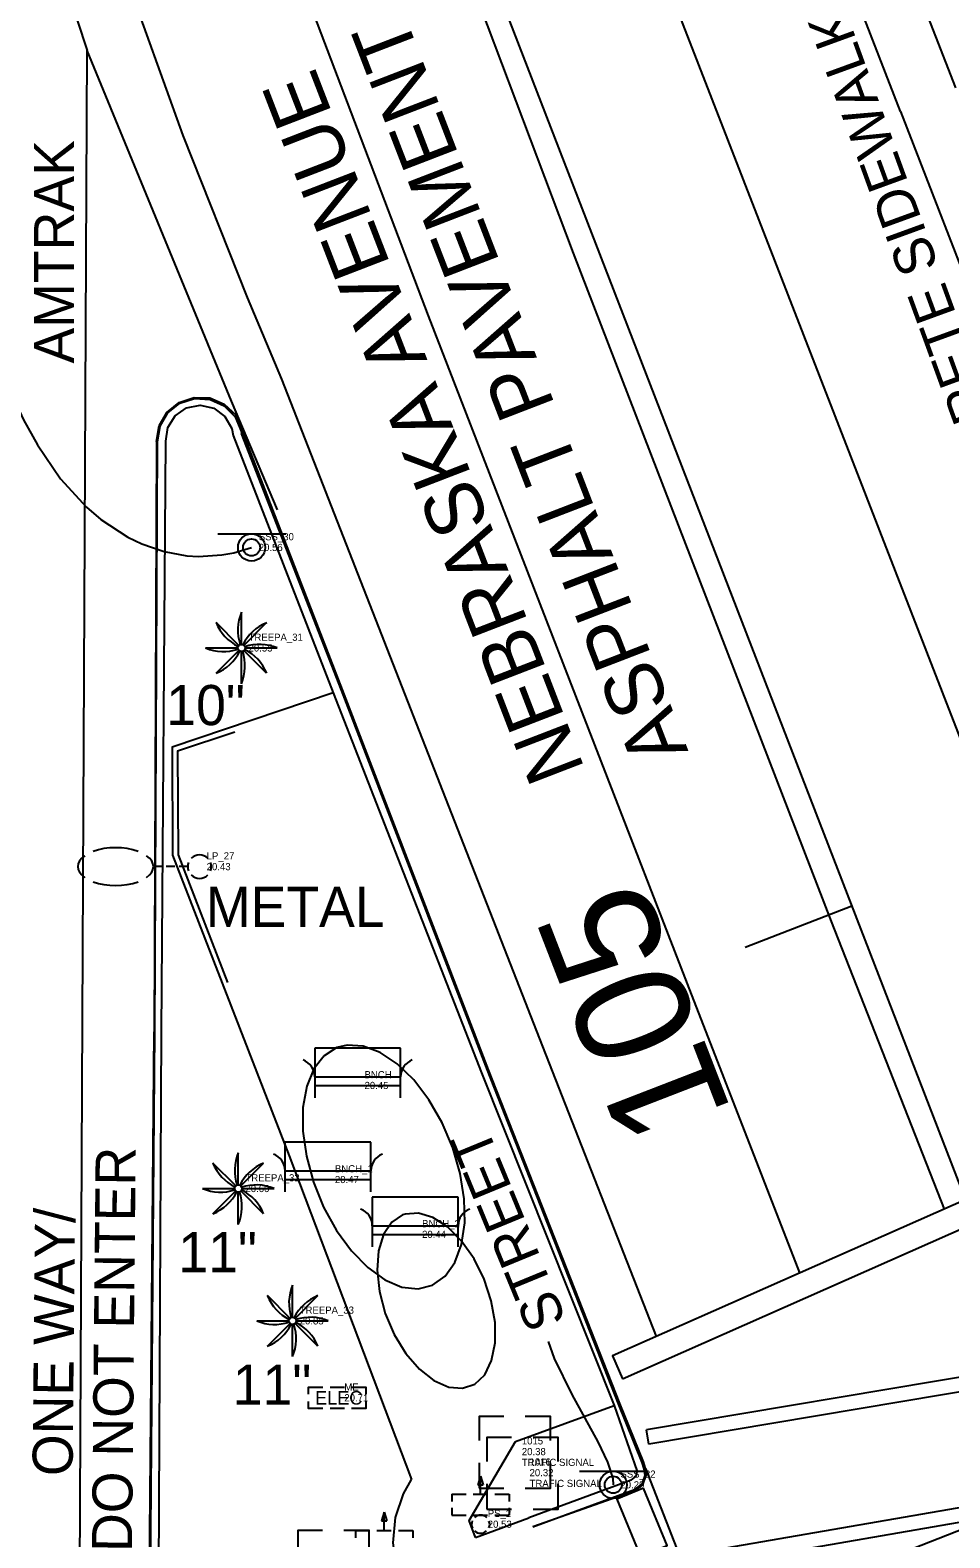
# Model space of a CAD drawing. Extents: x 509744 to 512285, y 1314862 to 1316822.
# Drawn here: x 510479.2 to 510543.5, y 1315469.6 to 1315574.9 of the extents above; entities that cross this region are included whole.
import ezdxf

# ---------------------------------------------------------------- set-up
doc = ezdxf.new("R2010")
doc.units = 0
for name, color, linetype in [('BaselineSurvey', 7, 'Continuous'), ('Bench_ep', 7, 'Continuous'), ('BusStop_ep', 7, 'Continuous'), ('CGBack_ep', 7, 'Continuous'), ('CGep_ep', 7, 'Continuous'), ('CGFace_ep', 7, 'Continuous'), ('ConcSlabs_ep', 7, 'Continuous'), ('CurbRampWarning_ep', 7, 'Continuous'), ('ElecAer_ep', 7, 'Continuous'), ('Luminaire_ep', 7, 'Continuous'), ('MeterElec_ep', 7, 'Continuous'), ('PavtAsphalt_ep', 7, 'Continuous'), ('PedSignal_ep', 7, 'Continuous'), ('PMRK_ep', 7, 'Continuous'), ('PullBox_ep', 7, 'Continuous'), ('Railing_ep', 7, 'Continuous'), ('SignSingle_ep', 7, 'Continuous'), ('TextBLStation', 7, 'Continuous'), ('TextElevLabel', 7, 'Continuous'), ('TextPtLabel', 7, 'Continuous'), ('TextSurveyLabel', 7, 'Continuous'), ('TextTopoLabel_ep', 7, 'Continuous'), ('TextUtilLabel_ep', 7, 'Continuous'), ('TreePalm_ep', 7, 'Continuous')]:
    doc.layers.add(name, color=color, linetype=linetype)

msp = doc.modelspace()

# ---------------------------------------------------------------- linework, layer by layer
at = {"layer": 'BaselineSurvey'}
for p, q in [((510773.86, 1314900.51), (510499.95, 1315608.68)), ((510536.67, 1315513.74), (510529.21, 1315510.85))]:
    msp.add_line(p, q, dxfattribs=at)
at = {"layer": 'Bench_ep'}
for p, q in [((510505.13, 1315503.82), (510499.13, 1315503.82)), ((510499.13, 1315503.82), (510499.13, 1315500.34)), ((510505.13, 1315500.34), (510505.13, 1315503.82)), ((510499.13, 1315501.81), (510505.13, 1315501.81)), ((510499.13, 1315501.21), (510505.13, 1315501.21)), ((510503.05, 1315497.25), (510497.05, 1315497.25)), ((510497.05, 1315497.25), (510497.05, 1315493.77)), ((510503.05, 1315493.77), (510503.05, 1315497.25)), ((510497.05, 1315495.25), (510503.05, 1315495.25)), ((510497.05, 1315494.64), (510503.05, 1315494.64)), ((510509.15, 1315493.41), (510503.15, 1315493.41)), ((510503.15, 1315493.41), (510503.15, 1315489.94)), ((510509.15, 1315489.94), (510509.15, 1315493.41)), ((510503.15, 1315491.41), (510509.15, 1315491.41)), ((510503.15, 1315490.81), (510509.15, 1315490.81))]:
    msp.add_line(p, q, dxfattribs=at)
for centre, start, end in [((510497.87, 1315501.81), 0.2359, 69.1544), ((510506.39, 1315501.81), 110.8456, 179.7641), ((510495.8, 1315495.24), 0.2359, 69.1544), ((510504.31, 1315495.24), 110.8456, 179.7641), ((510501.89, 1315491.4), 0.2359, 69.1544), ((510510.41, 1315491.4), 110.8456, 179.7641)]:
    msp.add_arc(centre, 1.26, start, end, dxfattribs=at)
at = {"layer": 'BusStop_ep'}
for points in [[(510500.68, 1315503.85), (510499.78, 1315503.28), (510499.06, 1315502.37), (510498.57, 1315501.15), (510498.31, 1315499.68), (510498.31, 1315498.02), (510498.55, 1315496.26), (510499.04, 1315494.46), (510499.75, 1315492.71), (510500.64, 1315491.08), (510501.69, 1315489.65), (510502.83, 1315488.49), (510504.02, 1315487.63), (510505.21, 1315487.13), (510506.35, 1315487.01), (510507.37, 1315487.26), (510508.25, 1315487.88), (510508.93, 1315488.85), (510509.39, 1315490.11), (510509.61, 1315491.61), (510509.58, 1315493.29), (510509.29, 1315495.06), (510508.77, 1315496.86), (510508.03, 1315498.6), (510507.11, 1315500.2), (510506.05, 1315501.59), (510504.9, 1315502.71), (510503.7, 1315503.51), (510502.52, 1315503.96), (510501.4, 1315504.03)], [(510505.27, 1315492.17), (510504.51, 1315491.65), (510503.93, 1315490.8), (510503.59, 1315489.66), (510503.49, 1315488.3), (510503.66, 1315486.82), (510504.06, 1315485.29), (510504.69, 1315483.82), (510505.5, 1315482.49), (510506.44, 1315481.4), (510507.46, 1315480.6), (510508.49, 1315480.14), (510509.46, 1315480.06), (510510.32, 1315480.36), (510511.01, 1315481.01), (510511.49, 1315481.99), (510511.74, 1315483.23), (510511.73, 1315484.65), (510511.47, 1315486.16), (510510.96, 1315487.68), (510510.26, 1315489.1), (510509.39, 1315490.34), (510508.41, 1315491.33), (510507.38, 1315491.99), (510506.37, 1315492.3), (510505.44, 1315492.23)]]:
    msp.add_lwpolyline(points, close=True, dxfattribs=at)
at = {"layer": 'CGBack_ep'}
for p, q in [((510488.42, 1315504.95), (510488.72, 1315546.2)), ((510488.2, 1315460.01), (510488.42, 1315504.95)), ((510521.24, 1315473.64), (510514.1, 1315471.02))]:
    msp.add_line(p, q, dxfattribs=at)
for points in [[(510488.72, 1315546.2), (510488.86, 1315547.16), (510489.37, 1315547.98), (510490.17, 1315548.53), (510491.12, 1315548.71), (510492.07, 1315548.5), (510492.85, 1315547.93), (510493.34, 1315547.09), (510493.44, 1315546.6)], [(510493.44, 1315546.6), (510500.43, 1315528.63), (510510.78, 1315502.1), (510520.05, 1315478.86), (510521.65, 1315474.26)], [(510521.24, 1315473.64), (510521.6, 1315473.93), (510521.65, 1315474.26)]]:
    msp.add_lwpolyline(points, dxfattribs=at)
at = {"layer": 'CGep_ep'}
msp.add_line((510521.5, 1315472.89), (510514.38, 1315470.39), dxfattribs=at)
for points in [[(510505.13, 1315670.88), (510507.7, 1315664.16), (510525.73, 1315617.49), (510543.9, 1315570.87)], [(510521.5, 1315472.89), (510522.06, 1315473.32), (510522.3, 1315473.99), (510522.24, 1315474.47)]]:
    msp.add_lwpolyline(points, dxfattribs=at)
at = {"layer": 'CGFace_ep'}
for p, q in [((510487.96, 1315504.95), (510488.15, 1315546.17)), ((510487.61, 1315460.03), (510487.96, 1315504.95)), ((510514.38, 1315470.39), (510521.47, 1315472.99))]:
    msp.add_line(p, q, dxfattribs=at)
for points in [[(510488.15, 1315546.17), (510488.32, 1315547.24), (510488.87, 1315548.18), (510489.71, 1315548.86), (510490.74, 1315549.18), (510491.82, 1315549.12), (510492.81, 1315548.67), (510493.56, 1315547.89), (510493.99, 1315546.89), (510494.02, 1315546.74)], [(510522.14, 1315474.44), (510522.02, 1315474.89), (510520.35, 1315478.97), (510511.2, 1315502.28), (510501, 1315528.82), (510494.02, 1315546.74)], [(510521.47, 1315472.99), (510522, 1315473.36), (510522.23, 1315473.97), (510522.14, 1315474.44)]]:
    msp.add_lwpolyline(points, dxfattribs=at)
at = {"layer": 'ConcSlabs_ep'}
for p, q in [((510513.17, 1315476.34), (510520.05, 1315478.86)), ((510510.37, 1315469.63), (510514.1, 1315471.02))]:
    msp.add_line(p, q, dxfattribs=at)
for points in [[(510500.43, 1315528.63), (510489.16, 1315524.82), (510489.2, 1315517.29), (510497.34, 1315496.29), (510505.9, 1315473.7)], [(510510.37, 1315469.63), (510509.93, 1315470.83), (510513.17, 1315476.34)], [(510504.84, 1315467.55), (510504.61, 1315469.28), (510504.77, 1315471.03), (510505.33, 1315472.69), (510505.9, 1315473.7)]]:
    msp.add_lwpolyline(points, dxfattribs=at)
at = {"layer": 'CurbRampWarning_ep'}
msp.add_lwpolyline([(510522.1, 1315473.09), (510520.24, 1315472.32), (510521.9, 1315468.31), (510523.75, 1315469.08)], close=True, dxfattribs=at)
at = {"layer": 'ElecAer_ep'}
msp.add_lwpolyline([(510459.75, 1315437.86), (510522.46, 1315461.64), (510586.32, 1315486.68), (510629.5, 1315501.86)], dxfattribs=at)
at = {"layer": 'Luminaire_ep'}
for p, q in [((510488.46, 1315516.49), (510487.86, 1315516.49)), ((510489.36, 1315516.49), (510488.76, 1315516.49)), ((510490.26, 1315516.49), (510489.66, 1315516.49))]:
    msp.add_line(p, q, dxfattribs=at)
for start, end in [(159.9115, 200.0885), (45, 135), (339.9115, 20.0885), (225, 315)]:
    msp.add_arc((510491.08, 1315516.49), 0.825, start, end, dxfattribs=at)
for start_param, end_param in [(4.075781, 5.348997), (5.668326, 6.898045), (2.526733, 3.756452), (0.934187, 2.207405)]:
    msp.add_ellipse((510485.22, 1315516.49), major_axis=(-2.64, 0), ratio=0.5, start_param=start_param, end_param=end_param, dxfattribs=at)
at = {"layer": 'MeterElec_ep'}
for points in [[(510498.7, 1315479.65), (510498.7, 1315480.15), (510499.7, 1315480.15)], [(510500.2, 1315480.15), (510501.2, 1315480.15)], [(510501.7, 1315480.15), (510502.7, 1315480.15), (510502.7, 1315479.65)], [(510499.7, 1315478.64), (510498.7, 1315478.64), (510498.7, 1315479.15)], [(510501.2, 1315478.64), (510500.2, 1315478.64)], [(510502.7, 1315479.15), (510502.7, 1315478.64), (510501.7, 1315478.64)]]:
    msp.add_lwpolyline(points, dxfattribs=at)
at = {"layer": 'PavtAsphalt_ep'}
for p, q in [((510488.08, 1315546.17), (510487.91, 1315504.95)), ((510487.52, 1315460.04), (510487.91, 1315504.95)), ((510522.24, 1315474.47), (510524.75, 1315468.01))]:
    msp.add_line(p, q, dxfattribs=at)
for points in [[(510488.08, 1315546.17), (510488.25, 1315547.26), (510488.8, 1315548.21), (510489.65, 1315548.91), (510490.7, 1315549.26), (510491.8, 1315549.22), (510492.81, 1315548.79), (510493.61, 1315548.03), (510494.08, 1315547.03), (510494.14, 1315546.77)], [(510522.24, 1315474.47), (510522.1, 1315474.92), (510520.46, 1315479), (510511.27, 1315502.31), (510501.06, 1315528.84), (510494.14, 1315546.77)]]:
    msp.add_lwpolyline(points, dxfattribs=at)
at = {"layer": 'PedSignal_ep'}
for p, q in [((510510.71, 1315473.93), (510510.52, 1315473.33)), ((510510.71, 1315472.66), (510510.71, 1315473.93)), ((510510.71, 1315473.93), (510510.91, 1315473.33)), ((510508.71, 1315472.66), (510509.71, 1315472.66)), ((510508.71, 1315472.66), (510508.71, 1315472.15)), ((510510.21, 1315472.66), (510511.21, 1315472.66)), ((510510.52, 1315473.33), (510510.91, 1315473.33)), ((510511.71, 1315472.66), (510512.71, 1315472.66)), ((510512.71, 1315472.66), (510512.71, 1315472.15)), ((510503.98, 1315471.41), (510503.79, 1315470.81)), ((510503.98, 1315470.13), (510503.98, 1315471.41)), ((510503.98, 1315471.41), (510504.18, 1315470.81)), ((510508.71, 1315471.72), (510508.71, 1315471.21)), ((510512.71, 1315471.72), (510512.71, 1315471.21)), ((510503.79, 1315470.81), (510504.18, 1315470.81)), ((510508.71, 1315471.21), (510509.71, 1315471.21)), ((510510.21, 1315471.21), (510511.21, 1315471.21)), ((510511.71, 1315471.21), (510512.71, 1315471.21)), ((510501.98, 1315470.13), (510502.98, 1315470.13)), ((510501.98, 1315470.13), (510501.98, 1315469.62)), ((510503.48, 1315470.13), (510504.48, 1315470.13)), ((510504.98, 1315470.13), (510505.98, 1315470.13)), ((510505.98, 1315470.13), (510505.98, 1315469.62))]:
    msp.add_line(p, q, dxfattribs=at)
for centre, radius, start, end in [((510510.86, 1315470.59), 0.766, 163.8832, 202.8498), ((510510.71, 1315470.59), 0.616, 45.0677, 132.9221), ((510510.93, 1315470.55), 0.437, 329.0362, 30.9638), ((510510.72, 1315470.55), 0.617, 227.1045, 312.8955)]:
    msp.add_arc(centre, radius, start, end, dxfattribs=at)
at = {"layer": 'PMRK_ep'}
for p, q in [((510482.71, 1315465.66), (510483.24, 1315573.48)), ((510574.85, 1315485.98), (510522.32, 1315477.15)), ((510575.01, 1315484.99), (510522.48, 1315476.16)), ((510583.22, 1315478.49), (510525.97, 1315468.56)), ((510522.48, 1315476.16), (510522.32, 1315477.15)), ((510582.74, 1315477.39), (510526.14, 1315467.57))]:
    msp.add_line(p, q, dxfattribs=at)
for points in [[(510540.07, 1315569.22), (510521.97, 1315615.86), (510503.06, 1315665.15)], [(510467.81, 1315662.15), (510469.21, 1315650.05), (510470.99, 1315638), (510473.18, 1315626.02), (510475.75, 1315614.12), (510478.72, 1315602.31), (510482.07, 1315590.6), (510485.8, 1315579.01), (510489.92, 1315567.55), (510494.4, 1315556.23), (510496.82, 1315550.53)], [(510495.93, 1315650.67), (510510.94, 1315611.1), (510529.06, 1315564.46), (510547.19, 1315517.82), (510555.03, 1315497.85)], [(510465.6, 1315644), (510467.93, 1315630.97), (510470.66, 1315618.01), (510473.77, 1315605.14), (510477.28, 1315592.37), (510481.17, 1315579.72), (510483.24, 1315573.48)], [(510505.16, 1315591.19), (510517.18, 1315559.33), (510535.22, 1315512.66), (510543.12, 1315492.58)], [(510494.86, 1315587.1), (510507.06, 1315554.95), (510525.15, 1315508.31), (510533.01, 1315488.12)], [(510496.53, 1315541.41), (510493.31, 1315548.99), (510483.24, 1315573.48)], [(510540.07, 1315569.22), (510558.16, 1315522.57), (510567.11, 1315499.75)], [(510496.82, 1315550.53), (510515.04, 1315503.94), (510522.98, 1315483.68)]]:
    msp.add_lwpolyline(points, dxfattribs=at)
msp.add_lwpolyline([(510520.64, 1315480.73), (510556.36, 1315496.52), (510555.65, 1315498.12), (510519.93, 1315482.33)], close=True, dxfattribs=at)
at = {"layer": 'PullBox_ep'}
for points in [[(510512.34, 1315478.09), (510510.61, 1315478.09), (510510.61, 1315476.41)], [(510515.61, 1315476.41), (510515.61, 1315478.09), (510513.84, 1315478.09)], [(510512.89, 1315476.62), (510511.15, 1315476.62), (510511.15, 1315474.94)], [(510516.15, 1315474.94), (510516.15, 1315476.62), (510514.39, 1315476.62)], [(510510.61, 1315474.86), (510510.61, 1315473.09)], [(510513.84, 1315473.09), (510515.61, 1315473.09), (510515.61, 1315474.86)], [(510511.15, 1315473.39), (510511.15, 1315471.62)], [(510514.39, 1315471.62), (510516.15, 1315471.62), (510516.15, 1315473.39)], [(510510.61, 1315473.09), (510512.34, 1315473.09)], [(510511.15, 1315471.62), (510512.89, 1315471.62)], [(510499.67, 1315470.12), (510497.94, 1315470.12), (510497.94, 1315468.45)], [(510502.94, 1315468.45), (510502.94, 1315470.12), (510501.17, 1315470.12)]]:
    msp.add_lwpolyline(points, dxfattribs=at)
at = {"layer": 'Railing_ep'}
msp.add_lwpolyline([(510493.55, 1315525.88), (510489.54, 1315524.55), (510489.6, 1315517.32), (510493.03, 1315508.39)], dxfattribs=at)
at = {"layer": 'SignSingle_ep'}
for p, q in [((510492.35, 1315539.73), (510497.1, 1315539.73)), ((510517.62, 1315474.27), (510522.37, 1315474.27))]:
    msp.add_line(p, q, dxfattribs=at)
for centre, radius in [((510494.72, 1315538.78), 0.95), ((510494.72, 1315538.78), 0.594), ((510519.99, 1315473.32), 0.95), ((510519.99, 1315473.32), 0.594)]:
    msp.add_circle(centre, radius, dxfattribs=at)
at = {"layer": 'TextTopoLabel_ep'}
for points in [[(510477.15, 1315551.59), (510478.2, 1315548.94), (510478.79, 1315547.69), (510479.75, 1315545.94), (510481.37, 1315543.58), (510483.19, 1315541.58), (510484.18, 1315540.73), (510486.07, 1315539.5), (510487.06, 1315539.02), (510488.61, 1315538.49), (510490.2, 1315538.2), (510491.01, 1315538.15), (510492.65, 1315538.26), (510493.48, 1315538.41), (510494.72, 1315538.78)], [(510515.45, 1315483.33), (510515.87, 1315482.15), (510517.1, 1315479.62), (510518.9, 1315476.32), (510519.58, 1315474.91), (510519.96, 1315473.76), (510519.99, 1315473.32)]]:
    msp.add_lwpolyline(points, dxfattribs=at)
at = {"layer": 'TreePalm_ep'}
for p, q in [((510493.83, 1315531.94), (510492.24, 1315533.53)), ((510494.01, 1315532.01), (510494.01, 1315534.26)), ((510494.18, 1315531.94), (510495.77, 1315533.53)), ((510491.51, 1315531.76), (510493.76, 1315531.76)), ((510492.24, 1315529.99), (510493.83, 1315531.58)), ((510494.01, 1315529.26), (510494.01, 1315531.51)), ((510495.77, 1315529.99), (510494.18, 1315531.58)), ((510494.26, 1315531.76), (510496.51, 1315531.76)), ((510493.61, 1315494.19), (510492.02, 1315495.78)), ((510493.79, 1315494.26), (510493.79, 1315496.51)), ((510493.96, 1315494.19), (510495.55, 1315495.78)), ((510491.29, 1315494.01), (510493.54, 1315494.01)), ((510492.02, 1315492.25), (510493.61, 1315493.84)), ((510493.79, 1315491.51), (510493.79, 1315493.76)), ((510495.55, 1315492.25), (510493.96, 1315493.84)), ((510494.04, 1315494.01), (510496.29, 1315494.01)), ((510497.58, 1315485.02), (510497.58, 1315487.27)), ((510497.41, 1315484.94), (510495.82, 1315486.53)), ((510497.76, 1315484.94), (510499.35, 1315486.53)), ((510495.08, 1315484.77), (510497.33, 1315484.77)), ((510495.82, 1315483), (510497.41, 1315484.59)), ((510497.58, 1315482.27), (510497.58, 1315484.52)), ((510499.35, 1315483), (510497.76, 1315484.59)), ((510497.83, 1315484.77), (510500.08, 1315484.77))]:
    msp.add_line(p, q, dxfattribs=at)
for centre in [(510494.01, 1315531.76), (510493.79, 1315494.01), (510497.58, 1315484.77)]:
    msp.add_circle(centre, 0.25, dxfattribs=at)
for centre, start, end in [((510495.24, 1315534.77), 202.3801, 243.2114), ((510497.01, 1315533.01), 157.3801, 198.2114), ((510497.01, 1315530.52), 112.3801, 153.2114), ((510492.76, 1315534.76), 247.3801, 288.2114), ((510491, 1315533), 292.3801, 333.2114), ((510491.01, 1315530.51), 337.3801, 18.2114), ((510492.77, 1315528.76), 22.3801, 63.2114), ((510495.26, 1315528.76), 67.3801, 108.2114), ((510495.02, 1315497.02), 202.3801, 243.2114), ((510496.79, 1315495.26), 157.3801, 198.2114), ((510496.79, 1315492.78), 112.3801, 153.2114), ((510492.54, 1315497.01), 247.3801, 288.2114), ((510490.78, 1315495.25), 292.3801, 333.2114), ((510490.79, 1315492.76), 337.3801, 18.2114), ((510492.55, 1315491.01), 22.3801, 63.2114), ((510495.04, 1315491.01), 67.3801, 108.2114), ((510500.58, 1315486.02), 157.3801, 198.2114), ((510498.82, 1315487.77), 202.3801, 243.2114), ((510500.59, 1315483.53), 112.3801, 153.2114), ((510498.83, 1315481.77), 67.3801, 108.2114), ((510496.33, 1315487.77), 247.3801, 288.2114), ((510494.58, 1315486), 292.3801, 333.2114), ((510494.58, 1315483.52), 337.3801, 18.2114), ((510496.35, 1315481.76), 22.3801, 63.2114)]:
    msp.add_arc(centre, 3.25, start, end, dxfattribs=at)

# ---------------------------------------------------------------- texts
at = {"layer": 'BaselineSurvey'}
msp.add_text('105', height=8, rotation=111.1462, dxfattribs=at).set_placement((510528.32, 1315499.27))
at = {"layer": 'MeterElec_ep'}
msp.add_text('ELEC', height=0.95, dxfattribs=at).set_placement((510499.15, 1315478.92))
at = {"layer": 'TextBLStation'}
msp.add_text('105', height=8, rotation=111.1462, dxfattribs=at).set_placement((510528.32, 1315499.27))
at = {"layer": 'TextElevLabel'}
for s, p in [('20.56', (510495.22, 1315538.53)), ('20.55', (510494.51, 1315531.51)), ('20.43', (510491.58, 1315516.24)), ('20.45', (510502.61, 1315500.96)), ('20.47', (510500.54, 1315494.39)), ('20.60', (510494.29, 1315493.76)), ('20.44', (510506.63, 1315490.56)), ('20.85', (510498.08, 1315484.52)), ('20.71', (510501.2, 1315479.15)), ('20.38', (510513.6, 1315475.39)), ('20.32', (510514.14, 1315473.92)), ('20.29', (510520.49, 1315473.07)), ('20.53', (510511.22, 1315470.32))]:
    msp.add_text(s, height=0.5, dxfattribs=at).set_placement(p)
at = {"layer": 'TextPtLabel'}
for s, p in [('SSS_30', (510495.22, 1315539.28)), ('TREEPA_31', (510494.51, 1315532.26)), ('LP_27', (510491.58, 1315516.99)), ('BNCH', (510502.61, 1315501.71)), ('BNCH_1', (510500.54, 1315495.14)), ('TREEPA_32', (510494.29, 1315494.51)), ('BNCH_2', (510506.63, 1315491.31)), ('TREEPA_33', (510498.08, 1315485.27)), ('ME', (510501.2, 1315479.9)), ('1015', (510513.6, 1315476.14)), ('1016', (510514.14, 1315474.67)), ('SSS_32', (510520.49, 1315473.82)), ('PS_2', (510511.22, 1315471.07))]:
    msp.add_text(s, height=0.5, dxfattribs=at).set_placement(p)
at = {"layer": 'TextSurveyLabel'}
for p in [(510513.6, 1315474.64), (510514.14, 1315473.17)]:
    msp.add_text('TRAFIC SIGNAL', height=0.5, dxfattribs=at).set_placement(p)
at = {"layer": 'TextTopoLabel_ep'}
for s, height, rotation, p in [('CONCRETE SIDEWALK', 2.8, 110.0064, (510550.3, 1315537.69)), ('ASPHALT PAVEMENT', 4, 111.0737, (510525.25, 1315524.55)), ('NEBRASKA AVENUE', 4, 111.0737, (510518.02, 1315523.29)), ('AMTRAK', 2.8, 90, (510482.32, 1315551.62)), ('DO NOT ENTER', 2.8, 89.4623, (510486.36, 1315468.62)), ('STREET', 2.8, 112.375, (510516.74, 1315484.81)), ('ONE WAY/', 2.8, 89.4623, (510482.21, 1315473.92))]:
    msp.add_text(s, height=height, rotation=rotation, dxfattribs=at).set_placement(p)
for s, p in [('10"', (510488.76, 1315526.37)), ('11"', (510489.6, 1315488.17)), ('11"', (510493.4, 1315478.92))]:
    msp.add_text(s, height=2.8, dxfattribs=at).set_placement(p)
at = {"layer": 'TextUtilLabel_ep'}
msp.add_text('METAL', height=2.8, dxfattribs=at).set_placement((510491.53, 1315512.28))

doc.saveas('drawing.dxf')
